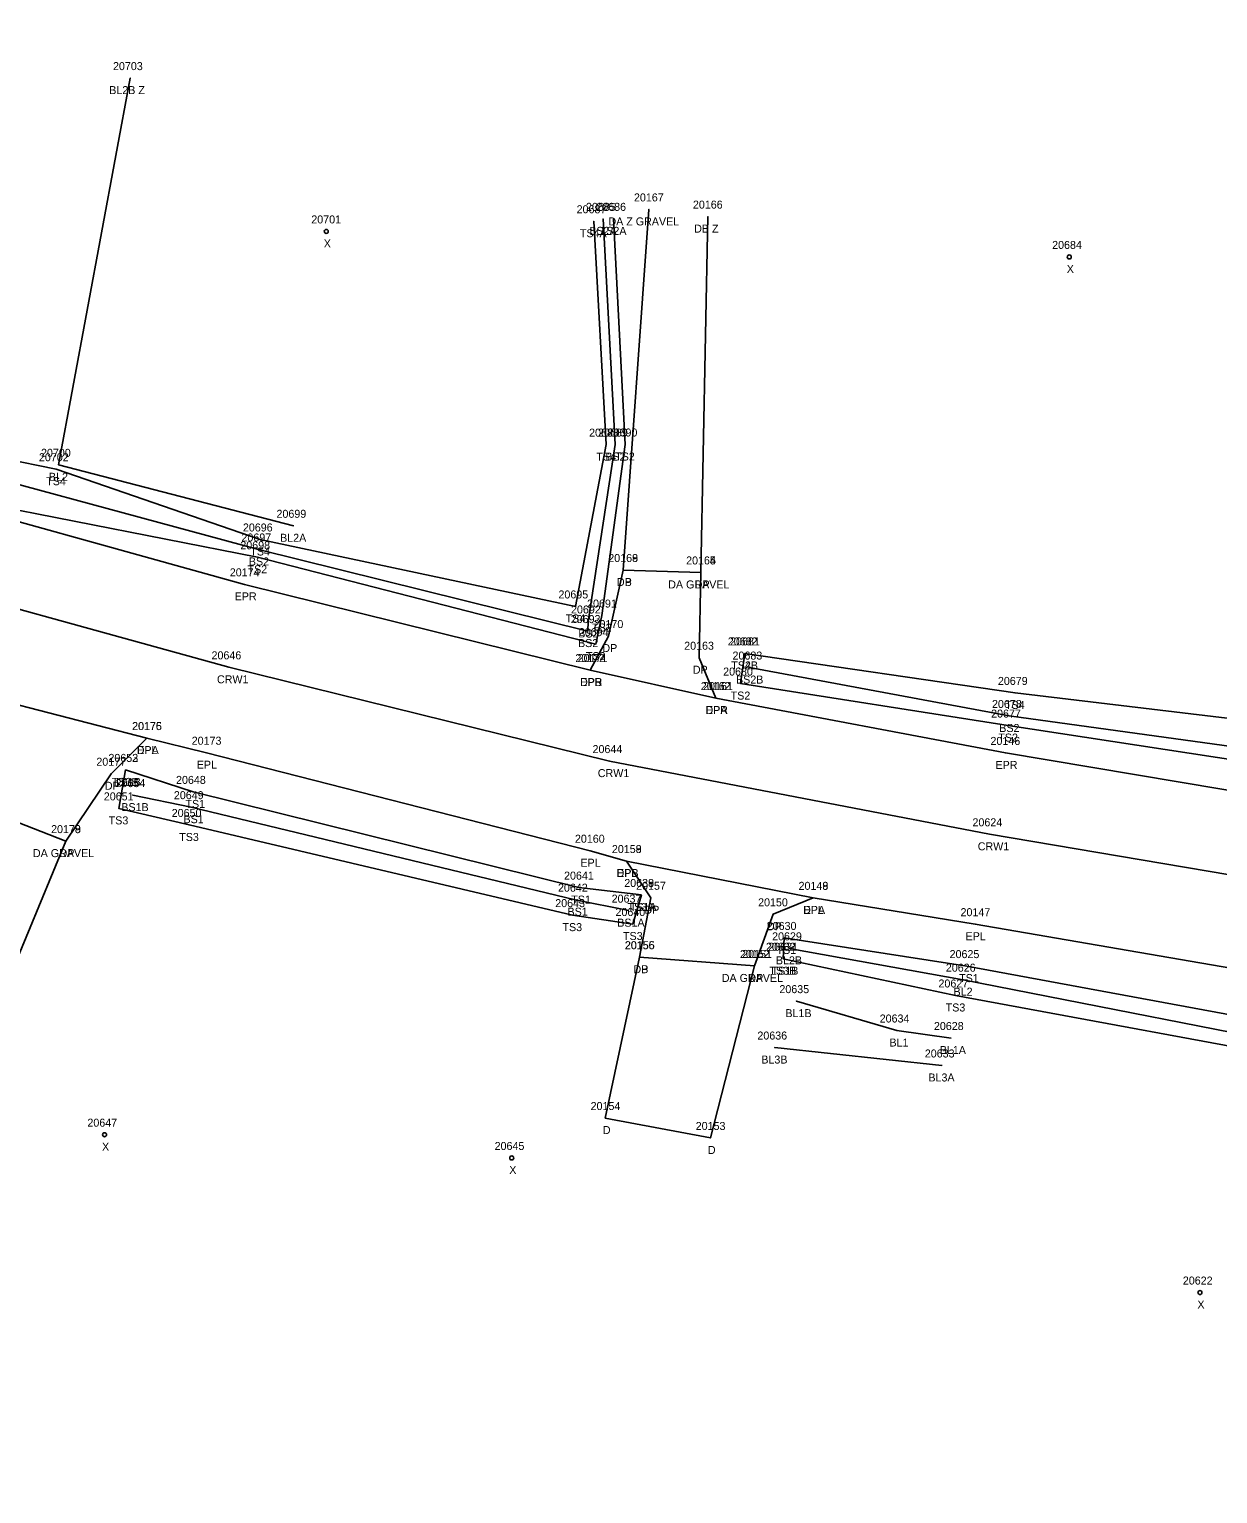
# Model space of a CAD drawing. Extents: x 1813127 to 1814107, y 1178171 to 1179078.
# Drawn here: x 1813328.5 to 1813477.1, y 1178703.5 to 1178886.5 of the extents above; entities that cross this region are included whole.
import ezdxf

# ---------------------------------------------------------------- set-up
doc = ezdxf.new("R2010")
doc.units = 0
for name, color, linetype in [('RD_DTM_BkLn1', 7, 'Continuous'), ('RD_DTM_BkLn2', 7, 'Continuous'), ('RD_EX_Driveway', 7, 'Continuous'), ('RD_EX_Driveway_txCode', 7, 'Continuous'), ('RD_EX_Road', 7, 'Continuous'), ('RD_EX_Road_txCode', 7, 'Continuous'), ('RD_SMD_Locator', 7, 'Continuous'), ('RD_SMD_Misc', 7, 'Continuous')]:
    doc.layers.add(name, color=color, linetype=linetype)

msp = doc.modelspace()

# ---------------------------------------------------------------- linework, layer by layer
at = {"layer": 'RD_DTM_BkLn1'}
msp.add_line((1813442.63, 1178757), (1813421.73, 1178759.24), dxfattribs=at)
for points in [[(1813361.58, 1178824.45), (1813332.19, 1178832.07), (1813341.16, 1178880.4)], [(1813740.76, 1178717.86), (1813693.97, 1178742.65), (1813652.18, 1178753.85), (1813643.74, 1178755.64), (1813595, 1178763.51), (1813546.44, 1178770.61), (1813497.6, 1178777.62), (1813448.59, 1178785.89), (1813401.09, 1178795.04), (1813353.48, 1178806.76), (1813306.05, 1178819.85), (1813260.03, 1178834.12), (1813213.64, 1178849.47), (1813166.61, 1178866.29)], [(1813521.54, 1178735.83), (1813516.61, 1178745.01), (1813509.8, 1178754.82), (1813493.76, 1178758.2), (1813445.29, 1178767.72), (1813423.54, 1178771.64)], [(1813443.77, 1178760.43), (1813436.99, 1178761.37), (1813424.45, 1178765.04)]]:
    msp.add_lwpolyline(points, dxfattribs=at)
at = {"layer": 'RD_DTM_BkLn2'}
for points in [[(1813399.11, 1178862.51), (1813400.66, 1178834.59), (1813396.83, 1178814.37), (1813357.41, 1178822.74), (1813331.9, 1178831.52), (1813325.37, 1178832.88), (1813310.54, 1178837.02), (1813266.49, 1178855.54), (1813220.54, 1178869.08), (1813171.6, 1178886.5)], [(1813400.27, 1178862.81), (1813401.78, 1178834.6), (1813398.4, 1178812.49), (1813398.37, 1178811.29), (1813357.2, 1178821.49), (1813308.85, 1178834.57), (1813264.85, 1178849.55), (1813219.03, 1178864.91), (1813170.13, 1178882.22)], [(1813401.59, 1178862.81), (1813403.02, 1178834.61), (1813400.13, 1178813.23), (1813399.37, 1178809.66), (1813357.07, 1178820.51), (1813311.17, 1178829.54), (1813264.4, 1178847.94), (1813218.33, 1178862.86), (1813169.73, 1178880.34)], [(1813510.57, 1178790.34), (1813499.73, 1178792.03), (1813450.92, 1178799.48), (1813417.46, 1178804.73), (1813418, 1178808.5)], [(1813514.81, 1178793.9), (1813500.27, 1178797.8), (1813451.77, 1178803.56), (1813418, 1178808.5)], [(1813518.26, 1178790.82), (1813499.66, 1178793.99), (1813451.03, 1178800.68), (1813418.59, 1178806.73)], [(1813405.06, 1178778.31), (1813404, 1178774.68), (1813396.43, 1178775.79), (1813348.52, 1178787.06), (1813339.71, 1178789.13), (1813340.57, 1178793.94)], [(1813405.06, 1178778.31), (1813397.25, 1178779.23), (1813349.02, 1178791.19), (1813340.57, 1178793.94)], [(1813403.48, 1178776.35), (1813396.77, 1178777.72), (1813348.76, 1178789.28), (1813341.46, 1178790.79)], [(1813728.98, 1178703.48), (1813680.74, 1178720.54), (1813670.9, 1178725.8), (1813665.35, 1178733.78), (1813654.36, 1178734.63), (1813647.32, 1178729.73), (1813639.1, 1178730.74), (1813591.11, 1178743.16), (1813543.28, 1178751.57), (1813511.7, 1178756.57), (1813494.92, 1178760.32), (1813445.74, 1178769.42), (1813422.91, 1178772.94), (1813422.78, 1178770.34)], [(1813509.01, 1178753.06), (1813492.62, 1178756.85), (1813444.34, 1178765.75), (1813422.78, 1178770.34)]]:
    msp.add_lwpolyline(points, dxfattribs=at)
at = {"layer": 'RD_EX_Driveway'}
for p, q in [((1813405.99, 1178863.99), (1813402.78, 1178818.92)), ((1813412.51, 1178818.62), (1813413.38, 1178863.09))]:
    msp.add_line(p, q, dxfattribs=at)
for points in [[(1813414.35, 1178802.92), (1813412.27, 1178807.96), (1813412.51, 1178818.62), (1813402.78, 1178818.92), (1813400.96, 1178810.67), (1813398.64, 1178806.42)], [(1813343.23, 1178797.92), (1813338.76, 1178793.46), (1813333.1, 1178785.04), (1813321.9, 1178789.4), (1813322.9, 1178794.86), (1813322.95, 1178797.03), (1813321.57, 1178801.49), (1813318.7, 1178804.23)], [(1813333.1, 1178785.04), (1813323.15, 1178761.04), (1813306.52, 1178767.93), (1813321.9, 1178789.4)], [(1813426.54, 1178777.95), (1813421.53, 1178775.89), (1813419.21, 1178769.44), (1813404.84, 1178770.53), (1813406.23, 1178777.96), (1813403.21, 1178782.55)], [(1813419.21, 1178769.44), (1813413.68, 1178747.94), (1813400.54, 1178750.43), (1813404.84, 1178770.53)]]:
    msp.add_lwpolyline(points, dxfattribs=at)
at = {"layer": 'RD_EX_Road'}
for points in [[(1813499.47, 1178787.87), (1813450.56, 1178796.06), (1813414.35, 1178802.92), (1813398.64, 1178806.42), (1813355.44, 1178817.13), (1813309.85, 1178829.79), (1813263.76, 1178844.1), (1813216.84, 1178859.81), (1813169.03, 1178877.13)], [(1813732.94, 1178707.95), (1813689.88, 1178731.75), (1813641.71, 1178744.36), (1813593.37, 1178752.09), (1813544.49, 1178758.77), (1813495.45, 1178766.29), (1813446.8, 1178774.66), (1813426.54, 1178777.95), (1813403.21, 1178782.55), (1813398.65, 1178783.84), (1813350.68, 1178796.09), (1813343.23, 1178797.92), (1813318.7, 1178804.23), (1813303.26, 1178808.85), (1813256.8, 1178823.17), (1813209.81, 1178838.91), (1813163.27, 1178855.57)]]:
    msp.add_lwpolyline(points, dxfattribs=at)
at = {"layer": 'RD_SMD_Locator'}
for centre, radius in [((1813341.16, 1178880.4), 0.001), ((1813405.99, 1178863.99), 0.001), ((1813413.38, 1178863.09), 0.001), ((1813365.67, 1178861.24), 0.25), ((1813399.11, 1178862.51), 0.001), ((1813400.27, 1178862.81), 0.001), ((1813401.59, 1178862.81), 0.001), ((1813458.55, 1178858.05), 0.25), ((1813400.66, 1178834.59), 0.001), ((1813401.78, 1178834.6), 0.001), ((1813403.02, 1178834.61), 0.001), ((1813332.19, 1178832.07), 0.001), ((1813331.9, 1178831.52), 0.001), ((1813361.58, 1178824.45), 0.001), ((1813357.41, 1178822.74), 0.001), ((1813357.2, 1178821.49), 0.001), ((1813357.07, 1178820.51), 0.001), ((1813355.44, 1178817.13), 0.001), ((1813402.78, 1178818.92), 0.001), ((1813402.78, 1178818.92), 0.001), ((1813412.51, 1178818.62), 0.001), ((1813412.51, 1178818.62), 0.001), ((1813396.83, 1178814.37), 0.001), ((1813398.4, 1178812.49), 0.001), ((1813400.13, 1178813.23), 0.001), ((1813398.37, 1178811.29), 0.001), ((1813400.96, 1178810.67), 0.001), ((1813399.37, 1178809.66), 0.001), ((1813412.27, 1178807.96), 0.001), ((1813418, 1178808.5), 0.001), ((1813418, 1178808.5), 0.001), ((1813353.48, 1178806.76), 0.001), ((1813398.64, 1178806.42), 0.001), ((1813398.64, 1178806.42), 0.001), ((1813418.59, 1178806.73), 0.001), ((1813417.46, 1178804.73), 0.001), ((1813414.35, 1178802.92), 0.001), ((1813414.35, 1178802.92), 0.001), ((1813451.77, 1178803.56), 0.001), ((1813451.03, 1178800.68), 0.001), ((1813450.92, 1178799.48), 0.001), ((1813343.23, 1178797.92), 0.001), ((1813343.23, 1178797.92), 0.001), ((1813350.68, 1178796.09), 0.001), ((1813450.56, 1178796.06), 0.001), ((1813338.76, 1178793.46), 0.001), ((1813340.57, 1178793.94), 0.001), ((1813340.57, 1178793.94), 0.001), ((1813401.09, 1178795.04), 0.001), ((1813341.46, 1178790.79), 0.001), ((1813349.02, 1178791.19), 0.001), ((1813339.71, 1178789.13), 0.001), ((1813348.76, 1178789.28), 0.001), ((1813348.52, 1178787.06), 0.001), ((1813333.1, 1178785.04), 0.001), ((1813333.1, 1178785.04), 0.001), ((1813448.59, 1178785.89), 0.001), ((1813398.65, 1178783.84), 0.001), ((1813403.21, 1178782.55), 0.001), ((1813403.21, 1178782.55), 0.001), ((1813397.25, 1178779.23), 0.001), ((1813396.77, 1178777.72), 0.001), ((1813405.06, 1178778.31), 0.001), ((1813405.06, 1178778.31), 0.001), ((1813406.23, 1178777.96), 0.001), ((1813426.54, 1178777.95), 0.001), ((1813426.54, 1178777.95), 0.001), ((1813396.43, 1178775.79), 0.001), ((1813403.48, 1178776.35), 0.001), ((1813421.53, 1178775.89), 0.001), ((1813404, 1178774.68), 0.001), ((1813446.8, 1178774.66), 0.001), ((1813422.91, 1178772.94), 0.001), ((1813423.54, 1178771.64), 0.001), ((1813404.84, 1178770.53), 0.001), ((1813404.84, 1178770.53), 0.001), ((1813422.78, 1178770.34), 0.001), ((1813422.78, 1178770.34), 0.001), ((1813419.21, 1178769.44), 0.001), ((1813419.21, 1178769.44), 0.001), ((1813445.29, 1178767.72), 0.001), ((1813445.74, 1178769.42), 0.001), ((1813424.45, 1178765.04), 0.001), ((1813444.34, 1178765.75), 0.001), ((1813436.99, 1178761.37), 0.001), ((1813443.77, 1178760.43), 0.001), ((1813421.73, 1178759.24), 0.001), ((1813442.63, 1178757), 0.001), ((1813400.54, 1178750.43), 0.001), ((1813337.94, 1178748.35), 0.25), ((1813413.68, 1178747.94), 0.001), ((1813388.85, 1178745.44), 0.25), ((1813474.89, 1178728.62), 0.25)]:
    msp.add_circle(centre, radius, dxfattribs=at)

# ---------------------------------------------------------------- texts
at = {"layer": 'RD_EX_Driveway_txCode'}
for s, p in [('20167', (1813404.13, 1178864.99)), ('20166', (1813411.5, 1178864.09)), ('DA Z GRAVEL', (1813400.94, 1178861.99)), ('DB Z', (1813411.66, 1178861.09)), ('20168', (1813400.92, 1178819.92)), ('20169', (1813400.92, 1178819.92)), ('20164', (1813410.65, 1178819.62)), ('20165', (1813410.65, 1178819.62)), ('DB', (1813402, 1178816.92)), ('DP', (1813402, 1178816.92)), ('DA GRAVEL', (1813408.41, 1178816.62)), ('DP', (1813411.73, 1178816.62)), ('20170', (1813399.08, 1178811.67)), ('20163', (1813410.41, 1178808.96)), ('20171', (1813397.09, 1178807.42)), ('DP', (1813400.18, 1178808.67)), ('DP', (1813411.49, 1178805.96)), ('DPB', (1813397.39, 1178804.42)), ('20162', (1813412.49, 1178803.92)), ('DPA', (1813413.08, 1178800.92)), ('20176', (1813341.38, 1178798.92)), ('20177', (1813336.92, 1178794.46)), ('DPA', (1813341.97, 1178795.92)), ('DP', (1813337.98, 1178791.46)), ('20178', (1813331.26, 1178786.04)), ('20179', (1813331.26, 1178786.04)), ('20158', (1813401.37, 1178783.55)), ('DA GRAVEL', (1813328.99, 1178783.04)), ('DP', (1813332.32, 1178783.04)), ('DPB', (1813401.96, 1178780.55)), ('20157', (1813404.4, 1178778.96)), ('20149', (1813424.71, 1178778.95)), ('DP', (1813405.45, 1178775.96)), ('20150', (1813419.65, 1178776.89)), ('DPA', (1813425.27, 1178775.95)), ('DP', (1813420.75, 1178773.89)), ('20156', (1813402.98, 1178771.53)), ('20155', (1813403.01, 1178771.53)), ('20152', (1813417.38, 1178770.44)), ('20151', (1813417.66, 1178770.44)), ('DB', (1813404.06, 1178768.53)), ('DP', (1813404.06, 1178768.53)), ('DA GRAVEL', (1813415.11, 1178767.44)), ('DP', (1813418.43, 1178767.44)), ('20154', (1813398.71, 1178751.43)), ('D', (1813400.24, 1178748.43)), ('20153', (1813411.85, 1178748.94)), ('D', (1813413.37, 1178745.94))]:
    msp.add_text(s, height=1, dxfattribs=at).set_placement(p)
at = {"layer": 'RD_EX_Road_txCode'}
for s, p in [('20174', (1813353.6, 1178818.13)), ('EPR', (1813354.21, 1178815.13)), ('20172', (1813396.81, 1178807.42)), ('EPR', (1813397.42, 1178804.42)), ('20161', (1813412.77, 1178803.92)), ('EPR', (1813413.12, 1178800.92)), ('20175', (1813341.4, 1178798.92)), ('20173', (1813348.84, 1178797.09)), ('20146', (1813448.7, 1178797.06)), ('EPL', (1813342.03, 1178795.92)), ('EPL', (1813349.47, 1178794.09)), ('EPR', (1813449.33, 1178794.06)), ('20160', (1813396.75, 1178784.84)), ('20159', (1813401.37, 1178783.55)), ('EPL', (1813397.44, 1178781.84)), ('EPL', (1813402, 1178780.55)), ('20148', (1813424.71, 1178778.95)), ('EPL', (1813425.34, 1178775.95)), ('20147', (1813444.96, 1178775.66)), ('EPL', (1813445.59, 1178772.66))]:
    msp.add_text(s, height=1, dxfattribs=at).set_placement(p)
at = {"layer": 'RD_SMD_Misc'}
for s, p in [('20703', (1813339, 1178881.4)), ('BL2B Z', (1813338.53, 1178878.4)), ('20685', (1813398.13, 1178863.81)), ('20686', (1813399.42, 1178863.81)), ('20701', (1813363.79, 1178862.24)), ('20687', (1813396.96, 1178863.51)), ('TS4A', (1813397.37, 1178860.51)), ('BS2A', (1813398.55, 1178860.81)), ('TS2A', (1813399.85, 1178860.81)), ('X', (1813365.35, 1178859.24)), ('20684', (1813456.41, 1178859.05)), ('X', (1813458.24, 1178856.05)), ('20688', (1813398.52, 1178835.59)), ('20689', (1813399.64, 1178835.6)), ('20690', (1813400.84, 1178835.61)), ('20700', (1813330, 1178833.07)), ('TS4', (1813399.42, 1178832.59)), ('BS2', (1813400.55, 1178832.6)), ('TS2', (1813401.78, 1178832.61)), ('20702', (1813329.74, 1178832.52)), ('TS4', (1813330.65, 1178829.52)), ('BL2', (1813330.99, 1178830.07)), ('20699', (1813359.44, 1178825.45)), ('20696', (1813355.24, 1178823.74)), ('20697', (1813355.06, 1178822.49)), ('BL2A', (1813359.89, 1178822.45)), ('20698', (1813354.92, 1178821.51)), ('TS4', (1813356.17, 1178820.74)), ('TS2', (1813355.82, 1178818.51)), ('BS2', (1813355.98, 1178819.49)), ('20695', (1813394.69, 1178815.37)), ('20692', (1813396.26, 1178813.49)), ('20691', (1813398.27, 1178814.23)), ('TS4', (1813395.59, 1178812.37)), ('20693', (1813396.23, 1178812.29)), ('20694', (1813397.23, 1178810.66)), ('TS2', (1813398.89, 1178811.23)), ('BS2', (1813397.14, 1178809.29)), ('BS2', (1813397.17, 1178810.49)), ('20682', (1813415.86, 1178809.5)), ('20681', (1813416.15, 1178809.5)), ('20646', (1813351.32, 1178807.76)), ('TS2', (1813398.12, 1178807.66)), ('20683', (1813416.45, 1178807.73)), ('20680', (1813415.28, 1178805.73)), ('TS2B', (1813416.29, 1178806.5)), ('TS4B', (1813416.29, 1178806.5)), ('CRW1', (1813352, 1178804.76)), ('BS2B', (1813416.89, 1178804.73)), ('20679', (1813449.63, 1178804.56)), ('TS2', (1813416.22, 1178802.73)), ('20678', (1813448.89, 1178801.68)), ('TS4', (1813450.53, 1178801.56)), ('20677', (1813448.78, 1178800.48)), ('BS2', (1813449.8, 1178798.68)), ('20644', (1813398.95, 1178796.04)), ('TS2', (1813449.68, 1178797.48)), ('20652', (1813338.43, 1178794.94)), ('20653', (1813338.43, 1178794.94)), ('CRW1', (1813399.61, 1178793.04)), ('TS3B', (1813338.85, 1178791.94)), ('TS1B', (1813339.14, 1178791.94)), ('20654', (1813339.32, 1178791.79)), ('20648', (1813346.88, 1178792.19)), ('20651', (1813337.85, 1178790.13)), ('BS1B', (1813340.04, 1178788.79)), ('20649', (1813346.61, 1178790.28)), ('TS1', (1813348.06, 1178789.19)), ('TS3', (1813338.46, 1178787.13)), ('20650', (1813346.34, 1178788.06)), ('BS1', (1813347.81, 1178787.28)), ('20624', (1813446.45, 1178786.89)), ('TS3', (1813347.28, 1178785.06)), ('CRW1', (1813447.11, 1178783.89)), ('20641', (1813395.39, 1178780.23)), ('20642', (1813394.63, 1178778.72)), ('20638', (1813402.92, 1178779.31)), ('20639', (1813402.92, 1178779.31)), ('20643', (1813394.29, 1178776.79)), ('TS1', (1813396.29, 1178777.23)), ('20637', (1813401.34, 1178777.35)), ('TS3A', (1813403.33, 1178776.31)), ('TS1A', (1813403.61, 1178776.31)), ('BS1', (1813395.82, 1178775.72)), ('20640', (1813401.82, 1178775.68)), ('BS1A', (1813402.04, 1178774.35)), ('TS3', (1813395.19, 1178773.79)), ('TS3', (1813402.76, 1178772.68)), ('20630', (1813420.73, 1178773.94)), ('20629', (1813421.4, 1178772.64)), ('20632', (1813420.63, 1178771.34)), ('20631', (1813420.92, 1178771.34)), ('TS1', (1813421.95, 1178770.94)), ('20625', (1813443.59, 1178770.42)), ('BL2B', (1813421.87, 1178769.64)), ('20626', (1813443.12, 1178768.72)), ('TS3B', (1813421.06, 1178768.34)), ('TS1B', (1813421.34, 1178768.34)), ('20627', (1813442.2, 1178766.75)), ('TS1', (1813444.78, 1178767.42)), ('20635', (1813422.31, 1178766.04)), ('BL2', (1813444.08, 1178765.72)), ('BL1B', (1813423.06, 1178763.04)), ('TS3', (1813443.1, 1178763.75)), ('20634', (1813434.85, 1178762.37)), ('20628', (1813441.63, 1178761.43)), ('20636', (1813419.56, 1178760.24)), ('BL1', (1813436.07, 1178759.37)), ('20633', (1813440.49, 1178758)), ('BL1A', (1813442.36, 1178758.43)), ('BL3B', (1813420.05, 1178757.24)), ('BL3A', (1813440.94, 1178755)), ('20647', (1813335.8, 1178749.35)), ('X', (1813337.63, 1178746.35)), ('20645', (1813386.71, 1178746.44)), ('X', (1813388.54, 1178743.44)), ('20622', (1813472.75, 1178729.62)), ('X', (1813474.57, 1178726.62))]:
    msp.add_text(s, height=1, dxfattribs=at).set_placement(p)

doc.saveas('drawing.dxf')
